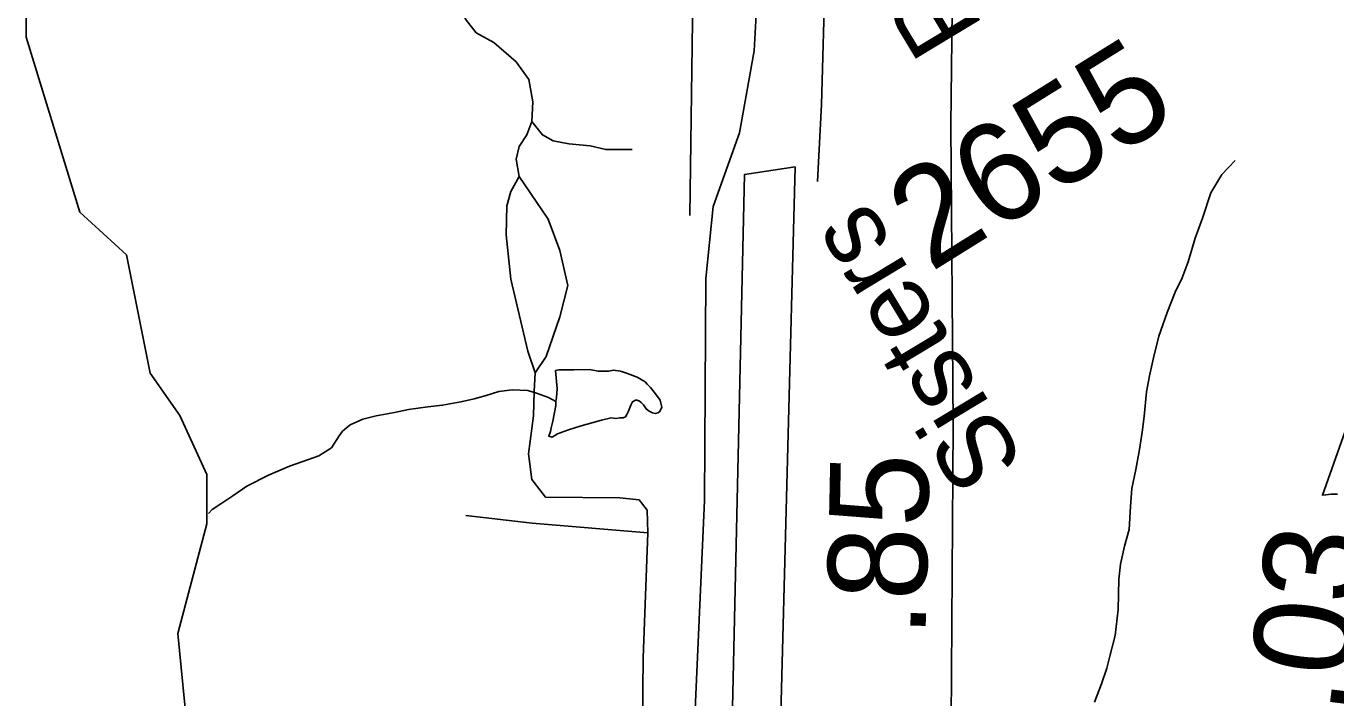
# Model space of a CAD drawing. Extents: x 2001466 to 31450019, y -30647475 to 847247.
# Drawn here: x 2165127 to 2168438, y 745745 to 747443 of the extents above; entities that cross this region are included whole.
import ezdxf

# ---------------------------------------------------------------- set-up
doc = ezdxf.new("R2010")
doc.units = 0
for name, color, linetype in [('Exist Aviation Commercial or Municipal Perimeter Paved', 7, 'Continuous'), ('Exist Hydrographic Creek Single Shore', 7, 'Continuous'), ('Exist Hydrographic Misc Water Feature', 7, 'Continuous'), ('Exist Road Non-System Type 51', 7, 'Continuous'), ('Exist Road Primary US Mileage Hundredths English Label', 7, 'Continuous'), ('Exist Road Primary US Shield CELL', 7, 'Continuous'), ('Exist Road Secondary Mileage Hundredths English Label', 7, 'Continuous'), ('Exist Road Secondary Type 51 Attributed', 7, 'Continuous'), ('Exist Road Secondary Type 51 Label', 7, 'Continuous'), ('Exist Road Secondary Type 51 Number Label', 7, 'Continuous')]:
    doc.layers.add(name, color=color, linetype=linetype)

msp = doc.modelspace()

# ---------------------------------------------------------------- linework, layer by layer
at = {"layer": 'Exist Aviation Commercial or Municipal Perimeter Paved'}
msp.add_lwpolyline([(2166909.6, 745607.9), (2166942.6, 747067.5), (2167070.6, 747087.2), (2167032.3, 745607.9)], dxfattribs=at)
at = {"layer": 'Exist Hydrographic Creek Single Shore'}
msp.add_lwpolyline([(2165559.1, 745607.9), (2165536.2, 745641.5), (2165510.1, 745907.8), (2165583.1, 746185), (2165583.1, 746309.8), (2165515.1, 746458.7), (2165440.2, 746565.3), (2165380.1, 746865), (2165262.2, 746972.4), (2165127.1, 747414.7), (2165126.8, 747475)], dxfattribs=at)
at = {"layer": 'Exist Hydrographic Misc Water Feature'}
for points in [[(2168183.4, 747103.5), (2168149.6, 747067.7), (2168121.9, 747021.6), (2168100.6, 746957.4), (2168082.3, 746907), (2168064.7, 746847.2), (2168049.1, 746807), (2168031.7, 746770.7), (2168011.6, 746719), (2167990, 746659), (2167976.3, 746604.6), (2167966.5, 746558.6), (2167959.1, 746518.4), (2167952.9, 746456.5), (2167947.6, 746416.7), (2167941.4, 746372.6), (2167932, 746322.5), (2167922.2, 746274.5), (2167918.9, 746228.4), (2167914.8, 746170.6), (2167903.1, 746128.6), (2167893.3, 746082.6), (2167889.4, 746044.6), (2167887.7, 745968.2), (2167880.1, 745902.4), (2167866.4, 745850.1), (2167858.8, 745820.1), (2167845.1, 745780.3), (2167827.4, 745733.9)], [(2166465.5, 746494), (2166465.9, 746484.2), (2166457.9, 746444), (2166454, 746427.9), (2166451.9, 746418.1), (2166447.8, 746406.1), (2166456.1, 746404.1), (2166469.6, 746412.2), (2166498.1, 746422.5), (2166530.1, 746432.7), (2166559.8, 746440.7), (2166581.5, 746446.8), (2166605.5, 746452.9), (2166617.6, 746451), (2166627.7, 746453.2), (2166635.9, 746453.2), (2166641.6, 746455.1), (2166645.5, 746461), (2166649.6, 746469.3), (2166655.2, 746485.1), (2166659.5, 746493.4), (2166667.5, 746497.5), (2166671.2, 746497.3), (2166677.3, 746495.2), (2166681.2, 746491.3), (2166687.6, 746485.5), (2166693.9, 746475.2), (2166701.9, 746469.6), (2166709.7, 746465.6), (2166717.9, 746463.5), (2166723.6, 746465.5), (2166727.5, 746467.7), (2166731.8, 746475.6), (2166733.3, 746479.8), (2166733.1, 746483.5), (2166731.6, 746489.8), (2166729.4, 746497.4), (2166717.3, 746513.5), (2166705, 746529.5), (2166697, 746537.6), (2166691.2, 746543.4), (2166671.2, 746555.4), (2166647.2, 746565.1), (2166629.1, 746571.1), (2166610.7, 746573), (2166599.4, 746571.1), (2166572.9, 746570.6), (2166551, 746574.7), (2166511, 746574.3), (2166482.9, 746574.1), (2166473.3, 746573.9), (2166465.3, 746572.3), (2166469.4, 746526.2), (2166467.5, 746504.2), (2166465.5, 746494)], [(2166465.5, 746494), (2166447.4, 746504), (2166419.3, 746513.9), (2166395.2, 746521.6), (2166355.6, 746523.5), (2166321.3, 746519.4), (2166289.3, 746509.2), (2166259.6, 746501.1), (2166225.6, 746492.9), (2166179.4, 746484.5), (2166141.9, 746480.4), (2166093.5, 746473.9), (2166057.8, 746465.9), (2166011.9, 746457.5), (2165977.7, 746449.3), (2165946.1, 746435.4), (2165926.4, 746418.9), (2165918, 746407.2), (2165898.5, 746376.9), (2165866.3, 746357), (2165826.5, 746342.7), (2165792.5, 746330.4), (2165739.2, 746308.1), (2165684.6, 746279.8), (2165649.2, 746255.5), (2165621.1, 746237.5), (2165597.3, 746221.2), (2165587.5, 746211.3)]]:
    msp.add_lwpolyline(points, dxfattribs=at)
at = {"layer": 'Exist Road Non-System Type 51'}
msp.add_line((2166814.6, 747700.4), (2166804.8, 746964.1), dxfattribs=at)
for points in [[(2166404.7, 747202.2), (2166407.2, 747251.5), (2166397.4, 747308.1), (2166365.4, 747352.4), (2166308.7, 747401.7), (2166264.4, 747426.3), (2166237.4, 747460.8), (2166190.6, 747639.3), (2166180.8, 747732.9)], [(2167087.6, 747700.6), (2167092.8, 747680.7), (2167132.2, 747626.5), (2167146.9, 747577.2), (2167137.1, 747244.8), (2167127.2, 747050.2)], [(2166974.6, 747518.1), (2166967.2, 747380.2), (2166930.3, 747173.4), (2166863.6, 746986.8), (2166845.2, 746805.3), (2166841.2, 746243.5), (2166812.6, 745602.7)], [(2166372.7, 747063.1), (2166365.4, 747106.2), (2166372.7, 747138.2), (2166392.4, 747167.8), (2166404.7, 747202.2)], [(2166404.7, 747202.2), (2166431.8, 747167.8), (2166458.9, 747153), (2166498.3, 747145.6), (2166552.4, 747140.7), (2166591.8, 747130.8), (2166658.3, 747130.8)], [(2166372.7, 747063.1), (2166352, 747025.2), (2166341.8, 746988.5), (2166339.8, 746915), (2166352, 746802.9), (2166394.8, 746621.4), (2166413.2, 746566.3)], [(2166441.1, 746607.7), (2166476.1, 746708.5), (2166495.8, 746787.3), (2166476.1, 746875.9), (2166446.6, 746954.7), (2166372.7, 747063.1)], [(2166441.1, 746607.7), (2166413.2, 746566.3)], [(2166698.5, 746162.1), (2166696.5, 746219.2), (2166676.1, 746245.7), (2166627.6, 746250.5), (2166439.7, 746252), (2166405, 746296.9), (2166396.9, 746362.2), (2166409.1, 746458), (2166411.1, 746519.2), (2166413.2, 746566.3)], [(2166698.5, 746162.1), (2166406, 746186.5), (2166238.6, 746206.2)], [(2166684.2, 745602.9), (2166686.3, 745845.8), (2166698.5, 746162.1)]]:
    msp.add_lwpolyline(points, dxfattribs=at)
at = {"layer": 'Exist Road Primary US Shield CELL'}
msp.add_lwpolyline([(2168441.4, 746260.1), (2168426.1, 746259.9), (2168412.1, 746258.5), (2168403.7, 746257), (2168513.7, 746566.9)], dxfattribs=at)
at = {"layer": 'Exist Road Secondary Type 51 Attributed'}
msp.add_lwpolyline([(2167091.1, 748127), (2167095, 748080.9), (2167097, 748061.3), (2167102.2, 748049), (2167111, 748037.9), (2167123, 748029.5), (2167133.5, 748023.8), (2167143.7, 748020.5), (2167185.6, 748018.9), (2167265.3, 748016.6), (2167336.6, 748014.3), (2167410.7, 748011.2), (2167431.6, 748009.7), (2167450.8, 748003.5), (2167466.3, 747988), (2167473.2, 747959.4), (2167471.2, 747774.4), (2167463.9, 747191.3), (2167470.1, 746433.2), (2167464.9, 745685.5)], dxfattribs=at)

# ---------------------------------------------------------------- texts
at = {"layer": 'Exist Road Primary US Mileage Hundredths English Label'}
msp.add_text('1.03', height=250, rotation=82.9691, dxfattribs=at).set_placement((2168435.1, 745515.1))
at = {"layer": 'Exist Road Secondary Mileage Hundredths English Label'}
msp.add_text('.85', height=250, rotation=88.8506, dxfattribs=at).set_placement((2167400.3, 745896.3))
at = {"layer": 'Exist Road Secondary Type 51 Label'}
for s, p in [('Rd.', (2167549.1, 747440.8)), ('Sisters', (2167653.2, 746341.6))]:
    msp.add_text(s, height=190, rotation=121.0969, dxfattribs=at).set_placement(p)
at = {"layer": 'Exist Road Secondary Type 51 Number Label'}
msp.add_text('2655', height=250, rotation=31.918, dxfattribs=at).set_placement((2167412.9, 746819.5))

doc.saveas('drawing.dxf')
